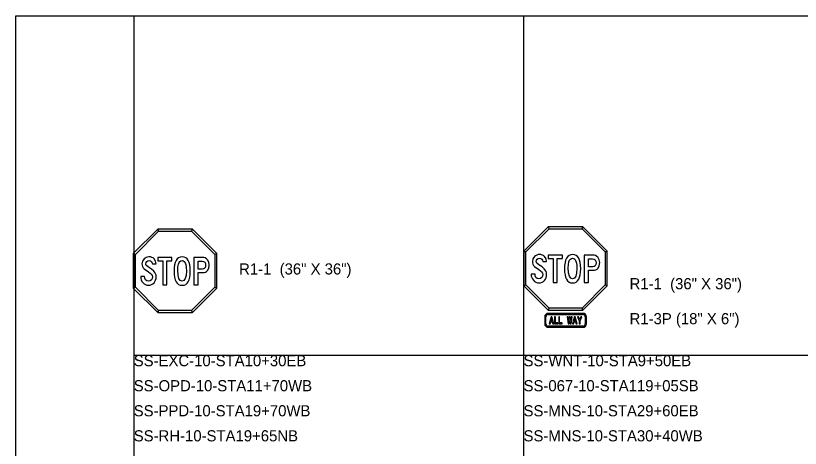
# Model space of a CAD drawing. Extents: x 1001568 to 1002149, y 1840825 to 1841423.
# Drawn here: x 1001886.41 to 1001914.59, y 1841095.12 to 1841110.67 of the extents above; entities that cross this region are included whole.
import ezdxf

# ---------------------------------------------------------------- set-up
doc = ezdxf.new("R2010")
doc.units = 0
for name, color, linetype in [('40', 7, 'Continuous'), ('R_No Plot', 7, 'Continuous'), ('SIGNS', 7, 'Continuous')]:
    doc.layers.add(name, color=color, linetype=linetype)

msp = doc.modelspace()

# ---------------------------------------------------------------- linework, layer by layer
at = {"layer": 'R_No Plot'}
for p, q in [((1001890.65, 1841110.667), (1001890.65, 1841048.127)), ((1001904.65, 1841110.667), (1001904.65, 1841048.127)), ((1001890.65, 1841098.469), (1001982.133, 1841098.469))]:
    msp.add_line(p, q, dxfattribs=at)
msp.add_lwpolyline([(1001886.411, 1841110.667), (1001964.232, 1841110.667), (1001964.232, 1841107.694), (1001968.454, 1841107.694), (1001968.454, 1841106.882), (1001982.133, 1841106.882), (1001982.133, 1841048.127), (1001886.411, 1841048.127)], close=True, dxfattribs=at)
at = {"layer": 'SIGNS'}
for p, q in [((1001905.534, 1841099.927), (1001905.534, 1841099.969)), ((1001906.784, 1841099.969), (1001905.534, 1841099.969)), ((1001906.784, 1841099.969), (1001906.784, 1841099.927)), ((1001905.409, 1841099.844), (1001905.451, 1841099.844)), ((1001905.409, 1841099.844), (1001905.409, 1841099.594)), ((1001906.868, 1841099.844), (1001906.909, 1841099.844)), ((1001906.909, 1841099.594), (1001906.909, 1841099.844)), ((1001905.451, 1841099.594), (1001905.409, 1841099.594)), ((1001905.534, 1841099.469), (1001905.534, 1841099.511)), ((1001905.534, 1841099.469), (1001906.784, 1841099.469)), ((1001906.784, 1841099.511), (1001906.784, 1841099.469)), ((1001906.909, 1841099.594), (1001906.868, 1841099.594))]:
    msp.add_line(p, q, dxfattribs=at)
for points in [[(1001905.538, 1841103.084), (1001904.659, 1841102.205), (1001904.732, 1841102.175), (1001905.568, 1841103.011), (1001905.538, 1841103.084), (1001905.538, 1841103.084)], [(1001906.781, 1841103.084), (1001905.538, 1841103.084), (1001905.568, 1841103.011), (1001906.75, 1841103.011), (1001906.781, 1841103.084), (1001906.781, 1841103.084)], [(1001907.659, 1841102.205), (1001906.781, 1841103.084), (1001906.75, 1841103.011), (1001907.586, 1841102.175), (1001907.659, 1841102.205), (1001907.659, 1841102.205)], [(1001891.514, 1841102.999), (1001890.636, 1841102.12), (1001890.709, 1841102.09), (1001891.545, 1841102.926), (1001891.514, 1841102.999), (1001891.514, 1841102.999)], [(1001892.757, 1841102.999), (1001891.514, 1841102.999), (1001891.545, 1841102.926), (1001892.727, 1841102.926), (1001892.757, 1841102.999), (1001892.757, 1841102.999)], [(1001893.636, 1841102.12), (1001892.757, 1841102.999), (1001892.727, 1841102.926), (1001893.563, 1841102.09), (1001893.636, 1841102.12), (1001893.636, 1841102.12)], [(1001904.659, 1841102.205), (1001904.659, 1841100.962), (1001904.732, 1841100.993), (1001904.732, 1841102.175), (1001904.659, 1841102.205), (1001904.659, 1841102.205)], [(1001907.659, 1841100.962), (1001907.659, 1841102.205), (1001907.586, 1841102.175), (1001907.586, 1841100.993), (1001907.659, 1841100.962), (1001907.659, 1841100.962)], [(1001890.636, 1841102.12), (1001890.636, 1841100.878), (1001890.709, 1841100.908), (1001890.709, 1841102.09), (1001890.636, 1841102.12), (1001890.636, 1841102.12)], [(1001890.903, 1841101.294), (1001890.903, 1841101.285), (1001890.907, 1841101.225), (1001890.921, 1841101.17), (1001890.945, 1841101.119), (1001890.979, 1841101.073), (1001891.021, 1841101.032), (1001891.069, 1841101.003), (1001891.122, 1841100.986), (1001891.18, 1841100.98), (1001891.239, 1841100.985), (1001891.292, 1841101.002), (1001891.339, 1841101.03), (1001891.381, 1841101.07), (1001891.414, 1841101.115), (1001891.437, 1841101.166), (1001891.452, 1841101.22), (1001891.456, 1841101.279), (1001891.451, 1841101.336), (1001891.434, 1841101.39), (1001891.407, 1841101.441), (1001891.368, 1841101.49), (1001891.294, 1841101.553), (1001891.18, 1841101.632), (1001891.105, 1841101.688), (1001891.089, 1841101.717), (1001891.083, 1841101.749), (1001891.092, 1841101.793), (1001891.119, 1841101.83), (1001891.157, 1841101.855), (1001891.202, 1841101.864), (1001891.251, 1841101.855), (1001891.286, 1841101.832), (1001891.305, 1841101.799), (1001891.32, 1841101.75), (1001891.456, 1841101.75), (1001891.434, 1841101.85), (1001891.382, 1841101.928), (1001891.344, 1841101.959), (1001891.301, 1841101.981), (1001891.252, 1841101.995), (1001891.198, 1841101.999), (1001891.148, 1841101.994), (1001891.102, 1841101.98), (1001891.06, 1841101.956), (1001891.021, 1841101.923), (1001890.965, 1841101.841), (1001890.947, 1841101.746), (1001890.952, 1841101.696), (1001890.966, 1841101.651), (1001890.989, 1841101.609), (1001891.022, 1841101.572), (1001891.181, 1841101.458), (1001891.241, 1841101.413), (1001891.277, 1841101.379), (1001891.31, 1841101.33), (1001891.321, 1841101.278), (1001891.311, 1841101.22), (1001891.283, 1841101.171), (1001891.237, 1841101.135), (1001891.18, 1841101.123), (1001891.12, 1841101.136), (1001891.074, 1841101.176), (1001891.046, 1841101.23), (1001891.038, 1841101.294)], [(1001891.696, 1841100.999), (1001891.838, 1841100.999), (1001891.838, 1841101.857), (1001892.021, 1841101.857), (1001892.021, 1841101.98), (1001891.517, 1841101.98), (1001891.517, 1841101.857), (1001891.696, 1841101.857)], [(1001893.636, 1841100.878), (1001893.636, 1841102.12), (1001893.563, 1841102.09), (1001893.563, 1841100.908), (1001893.636, 1841100.878), (1001893.636, 1841100.878)], [(1001904.926, 1841101.378), (1001904.926, 1841101.369), (1001904.93, 1841101.31), (1001904.945, 1841101.254), (1001904.969, 1841101.204), (1001905.002, 1841101.157), (1001905.045, 1841101.116), (1001905.093, 1841101.088), (1001905.146, 1841101.07), (1001905.204, 1841101.065), (1001905.262, 1841101.07), (1001905.316, 1841101.087), (1001905.363, 1841101.115), (1001905.405, 1841101.154), (1001905.438, 1841101.2), (1001905.461, 1841101.25), (1001905.475, 1841101.305), (1001905.48, 1841101.364), (1001905.474, 1841101.421), (1001905.458, 1841101.475), (1001905.43, 1841101.526), (1001905.392, 1841101.574), (1001905.318, 1841101.638), (1001905.204, 1841101.716), (1001905.129, 1841101.773), (1001905.113, 1841101.801), (1001905.107, 1841101.834), (1001905.116, 1841101.878), (1001905.142, 1841101.915), (1001905.18, 1841101.94), (1001905.226, 1841101.948), (1001905.274, 1841101.94), (1001905.31, 1841101.917), (1001905.329, 1841101.883), (1001905.344, 1841101.834), (1001905.48, 1841101.834), (1001905.458, 1841101.934), (1001905.406, 1841102.013), (1001905.368, 1841102.044), (1001905.325, 1841102.066), (1001905.276, 1841102.079), (1001905.222, 1841102.084), (1001905.172, 1841102.079), (1001905.126, 1841102.065), (1001905.083, 1841102.041), (1001905.045, 1841102.008), (1001904.989, 1841101.926), (1001904.971, 1841101.83), (1001904.975, 1841101.781), (1001904.989, 1841101.736), (1001905.013, 1841101.694), (1001905.046, 1841101.656), (1001905.205, 1841101.542), (1001905.264, 1841101.497), (1001905.301, 1841101.464), (1001905.333, 1841101.415), (1001905.344, 1841101.362), (1001905.335, 1841101.305), (1001905.307, 1841101.255), (1001905.261, 1841101.219), (1001905.204, 1841101.207), (1001905.144, 1841101.22), (1001905.097, 1841101.261), (1001905.07, 1841101.314), (1001905.062, 1841101.378)], [(1001905.719, 1841101.084), (1001905.862, 1841101.084), (1001905.862, 1841101.941), (1001906.045, 1841101.941), (1001906.045, 1841102.064), (1001905.54, 1841102.064), (1001905.54, 1841101.941), (1001905.719, 1841101.941)], [(1001890.636, 1841100.878), (1001891.514, 1841099.999), (1001891.545, 1841100.072), (1001890.709, 1841100.908), (1001890.636, 1841100.878), (1001890.636, 1841100.878)], [(1001892.757, 1841099.999), (1001893.636, 1841100.878), (1001893.563, 1841100.908), (1001892.727, 1841100.072), (1001892.757, 1841099.999), (1001892.757, 1841099.999)], [(1001904.659, 1841100.962), (1001905.538, 1841100.084), (1001905.568, 1841100.157), (1001904.732, 1841100.993), (1001904.659, 1841100.962), (1001904.659, 1841100.962)], [(1001906.781, 1841100.084), (1001907.659, 1841100.962), (1001907.586, 1841100.993), (1001906.75, 1841100.157), (1001906.781, 1841100.084), (1001906.781, 1841100.084)], [(1001891.514, 1841099.999), (1001892.757, 1841099.999), (1001892.727, 1841100.072), (1001891.545, 1841100.072), (1001891.514, 1841099.999), (1001891.514, 1841099.999)], [(1001906.784, 1841099.969), (1001905.534, 1841099.969), (1001905.534, 1841099.927), (1001906.784, 1841099.927), (1001906.784, 1841099.969), (1001906.784, 1841099.969)], [(1001905.538, 1841100.084), (1001906.781, 1841100.084), (1001906.75, 1841100.157), (1001905.568, 1841100.157), (1001905.538, 1841100.084), (1001905.538, 1841100.084)], [(1001905.409, 1841099.844), (1001905.409, 1841099.594), (1001905.451, 1841099.594), (1001905.451, 1841099.844), (1001905.409, 1841099.844), (1001905.409, 1841099.844)], [(1001905.76, 1841099.594), (1001905.886, 1841099.594), (1001905.886, 1841099.627), (1001905.795, 1841099.627), (1001905.795, 1841099.839), (1001905.76, 1841099.839)], [(1001905.912, 1841099.594), (1001906.038, 1841099.594), (1001906.038, 1841099.627), (1001905.947, 1841099.627), (1001905.947, 1841099.839), (1001905.912, 1841099.839)], [(1001906.253, 1841099.594), (1001906.285, 1841099.594), (1001906.306, 1841099.716), (1001906.33, 1841099.594), (1001906.36, 1841099.594), (1001906.4, 1841099.839), (1001906.365, 1841099.841), (1001906.343, 1841099.71), (1001906.32, 1841099.841), (1001906.292, 1841099.841), (1001906.268, 1841099.71), (1001906.247, 1841099.841), (1001906.212, 1841099.839)], [(1001906.703, 1841099.839), (1001906.662, 1841099.752), (1001906.62, 1841099.839), (1001906.583, 1841099.839), (1001906.644, 1841099.705), (1001906.644, 1841099.594), (1001906.679, 1841099.594), (1001906.679, 1841099.705), (1001906.741, 1841099.839)], [(1001906.909, 1841099.594), (1001906.909, 1841099.844), (1001906.868, 1841099.844), (1001906.868, 1841099.594), (1001906.909, 1841099.594), (1001906.909, 1841099.594)], [(1001905.534, 1841099.469), (1001906.784, 1841099.469), (1001906.784, 1841099.511), (1001905.534, 1841099.511), (1001905.534, 1841099.469), (1001905.534, 1841099.469)]]:
    msp.add_lwpolyline(points, close=True, dxfattribs=at)
for points in [[(1001892.682, 1841101.491), (1001892.677, 1841101.61), (1001892.664, 1841101.713), (1001892.641, 1841101.8), (1001892.61, 1841101.872), (1001892.569, 1841101.927), (1001892.519, 1841101.967), (1001892.46, 1841101.991), (1001892.392, 1841101.999), (1001892.323, 1841101.991), (1001892.264, 1841101.967), (1001892.213, 1841101.927), (1001892.172, 1841101.872), (1001892.14, 1841101.8), (1001892.117, 1841101.713), (1001892.103, 1841101.61), (1001892.099, 1841101.491), (1001892.103, 1841101.371), (1001892.116, 1841101.267), (1001892.139, 1841101.179), (1001892.17, 1841101.108), (1001892.211, 1841101.051), (1001892.26, 1841101.012), (1001892.319, 1841100.988), (1001892.386, 1841100.98), (1001892.456, 1841100.988), (1001892.516, 1841101.012), (1001892.566, 1841101.051), (1001892.608, 1841101.108), (1001892.64, 1841101.179), (1001892.663, 1841101.267), (1001892.677, 1841101.371), (1001892.682, 1841101.491)], [(1001893.111, 1841101.98), (1001892.809, 1841101.98), (1001892.809, 1841100.999), (1001892.962, 1841100.999), (1001892.962, 1841101.432), (1001893.118, 1841101.432), (1001893.175, 1841101.437), (1001893.224, 1841101.452), (1001893.267, 1841101.476), (1001893.303, 1841101.509), (1001893.347, 1841101.594), (1001893.362, 1841101.706), (1001893.346, 1841101.812), (1001893.296, 1841101.898), (1001893.258, 1841101.934), (1001893.214, 1841101.96), (1001893.165, 1841101.975), (1001893.111, 1841101.98)], [(1001906.706, 1841101.576), (1001906.701, 1841101.694), (1001906.687, 1841101.798), (1001906.665, 1841101.885), (1001906.633, 1841101.956), (1001906.592, 1841102.012), (1001906.543, 1841102.052), (1001906.484, 1841102.076), (1001906.416, 1841102.084), (1001906.347, 1841102.076), (1001906.287, 1841102.052), (1001906.237, 1841102.012), (1001906.196, 1841101.956), (1001906.163, 1841101.885), (1001906.141, 1841101.798), (1001906.127, 1841101.694), (1001906.122, 1841101.576), (1001906.126, 1841101.455), (1001906.14, 1841101.352), (1001906.162, 1841101.264), (1001906.194, 1841101.192), (1001906.234, 1841101.136), (1001906.284, 1841101.096), (1001906.342, 1841101.072), (1001906.41, 1841101.065), (1001906.479, 1841101.072), (1001906.539, 1841101.096), (1001906.59, 1841101.136), (1001906.632, 1841101.192), (1001906.664, 1841101.264), (1001906.687, 1841101.352), (1001906.701, 1841101.455), (1001906.706, 1841101.576)], [(1001906.565, 1841101.58), (1001906.555, 1841101.417), (1001906.526, 1841101.3), (1001906.478, 1841101.23), (1001906.412, 1841101.207), (1001906.344, 1841101.232), (1001906.295, 1841101.306), (1001906.266, 1841101.43), (1001906.257, 1841101.605), (1001906.263, 1841101.72), (1001906.281, 1841101.816), (1001906.304, 1841101.875), (1001906.333, 1841101.918), (1001906.369, 1841101.943), (1001906.412, 1841101.952), (1001906.454, 1841101.943), (1001906.489, 1841101.915), (1001906.519, 1841101.868), (1001906.541, 1841101.804), (1001906.559, 1841101.702), (1001906.565, 1841101.58)], [(1001907.135, 1841102.064), (1001906.832, 1841102.064), (1001906.832, 1841101.084), (1001906.986, 1841101.084), (1001906.986, 1841101.517), (1001907.141, 1841101.517), (1001907.198, 1841101.522), (1001907.248, 1841101.536), (1001907.291, 1841101.56), (1001907.327, 1841101.594), (1001907.371, 1841101.679), (1001907.386, 1841101.791), (1001907.369, 1841101.896), (1001907.32, 1841101.983), (1001907.281, 1841102.018), (1001907.238, 1841102.044), (1001907.189, 1841102.059), (1001907.135, 1841102.064)], [(1001907.137, 1841101.641), (1001906.986, 1841101.641), (1001906.986, 1841101.93), (1001907.128, 1841101.93), (1001907.183, 1841101.919), (1001907.223, 1841101.887), (1001907.247, 1841101.839), (1001907.255, 1841101.779), (1001907.247, 1841101.726), (1001907.224, 1841101.683), (1001907.186, 1841101.652), (1001907.137, 1841101.641)], [(1001892.541, 1841101.496), (1001892.531, 1841101.332), (1001892.502, 1841101.216), (1001892.455, 1841101.146), (1001892.388, 1841101.123), (1001892.32, 1841101.147), (1001892.272, 1841101.222), (1001892.243, 1841101.346), (1001892.233, 1841101.52), (1001892.239, 1841101.636), (1001892.258, 1841101.732), (1001892.28, 1841101.791), (1001892.309, 1841101.834), (1001892.345, 1841101.859), (1001892.388, 1841101.867), (1001892.43, 1841101.858), (1001892.466, 1841101.83), (1001892.495, 1841101.784), (1001892.517, 1841101.719), (1001892.535, 1841101.617), (1001892.541, 1841101.496)], [(1001893.114, 1841101.557), (1001892.962, 1841101.557), (1001892.962, 1841101.845), (1001893.104, 1841101.845), (1001893.159, 1841101.835), (1001893.2, 1841101.803), (1001893.224, 1841101.755), (1001893.232, 1841101.695), (1001893.224, 1841101.642), (1001893.2, 1841101.599), (1001893.163, 1841101.567), (1001893.114, 1841101.557)], [(1001905.576, 1841099.594), (1001905.612, 1841099.594), (1001905.628, 1841099.662), (1001905.681, 1841099.662), (1001905.698, 1841099.594), (1001905.734, 1841099.594), (1001905.672, 1841099.839), (1001905.638, 1841099.839), (1001905.576, 1841099.594)], [(1001905.637, 1841099.696), (1001905.654, 1841099.768), (1001905.672, 1841099.696), (1001905.637, 1841099.696)], [(1001906.412, 1841099.594), (1001906.448, 1841099.594), (1001906.464, 1841099.662), (1001906.517, 1841099.662), (1001906.535, 1841099.594), (1001906.571, 1841099.594), (1001906.509, 1841099.839), (1001906.474, 1841099.839), (1001906.412, 1841099.594)], [(1001906.473, 1841099.696), (1001906.49, 1841099.768), (1001906.509, 1841099.696), (1001906.473, 1841099.696)]]:
    msp.add_lwpolyline(points, dxfattribs=at)
for centre, radius, start, end in [((1001905.534, 1841099.844), 0.125, 90.0002, 179.9998), ((1001905.534, 1841099.844), 0.125, 90.0002, 179.9998), ((1001905.534, 1841099.844), 0.0833, 90.0002, 179.9998), ((1001906.784, 1841099.844), 0.125, 0, 90.0002), ((1001906.784, 1841099.844), 0.125, 0, 90.0002), ((1001906.784, 1841099.844), 0.0833, 0, 90.0002), ((1001905.534, 1841099.594), 0.125, 179.9998, 270.0001), ((1001905.534, 1841099.594), 0.125, 179.9998, 270.0001), ((1001905.534, 1841099.594), 0.0833, 179.9998, 270.0001), ((1001906.784, 1841099.594), 0.125, 270.0001, 0.0003), ((1001906.784, 1841099.594), 0.0833, 270.0001, 0.0003), ((1001906.784, 1841099.594), 0.125, 270.0001, 0.0003)]:
    msp.add_arc(centre, radius, start, end, dxfattribs=at)

# ---------------------------------------------------------------- texts
at = {"layer": '40'}
for s, p in [('R1-1  (36" X 36")', (1001894.434, 1841101.365)), ('R1-1  (36" X 36")', (1001908.458, 1841100.835)), ('R1-3P (18" X 6")', (1001908.458, 1841099.579)), ('SS-EXC-10-STA10+30EB', (1001890.65, 1841098.069)), ('SS-WNT-10-STA9+50EB', (1001904.65, 1841098.069)), ('SS-OPD-10-STA11+70WB', (1001890.65, 1841097.169)), ('SS-067-10-STA119+05SB', (1001904.65, 1841097.169)), ('SS-PPD-10-STA19+70WB', (1001890.65, 1841096.269)), ('SS-MNS-10-STA29+60EB', (1001904.65, 1841096.269)), ('SS-RH-10-STA19+65NB', (1001890.65, 1841095.369)), ('SS-MNS-10-STA30+40WB', (1001904.65, 1841095.369))]:
    msp.add_text(s, height=0.4, rotation=0, dxfattribs=at).set_placement(p)

doc.saveas('drawing.dxf')
